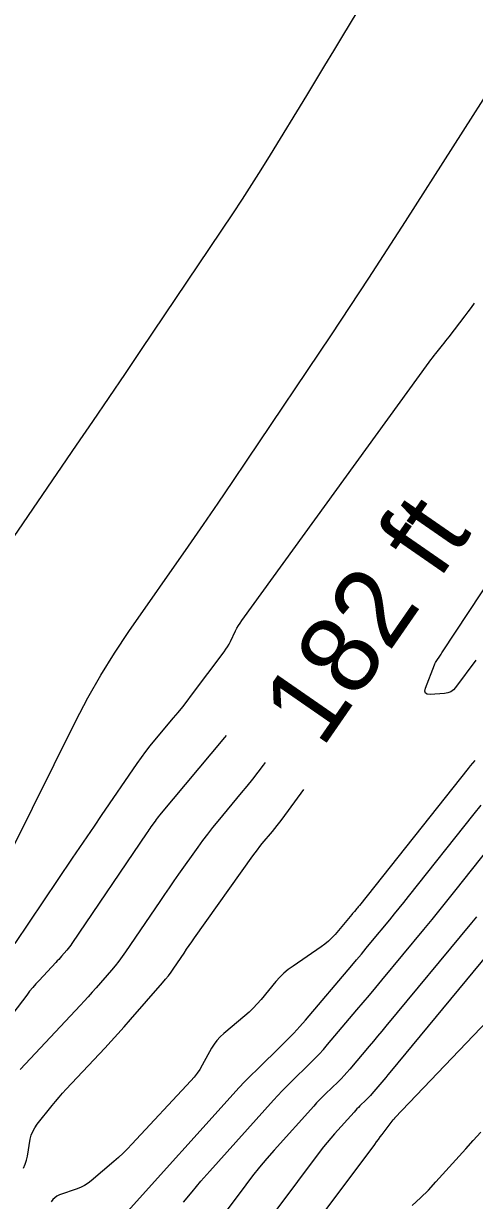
# Model space of a CAD drawing. Extents: x 7585033 to 7595090, y 547091 to 553471.
# Drawn here: x 7587281.3 to 7587317.3, y 548010.4 to 548104.5 of the extents above; entities that cross this region are included whole.
import ezdxf

# ---------------------------------------------------------------- set-up
doc = ezdxf.new("R2010")
doc.units = 0
for name, color, linetype in [('E_TERR_DSPLAY_GeneralTx', 7, 'Continuous'), ('E_TERR_DSPLAY_MajContour', 7, 'Continuous'), ('E_TERR_DSPLAY_MinContour', 7, 'Continuous')]:
    doc.layers.add(name, color=color, linetype=linetype)

msp = doc.modelspace()

# ---------------------------------------------------------------- linework, layer by layer
at = {"layer": 'E_TERR_DSPLAY_MajContour'}
for points in [[(7587316.39, 548119.453), (7587306.779, 548103.554), (7587306.057, 548102.36), (7587305.334, 548101.168), (7587304.61, 548099.976), (7587303.885, 548098.784), (7587300.983, 548094.02), (7587300.252, 548092.833), (7587299.506, 548091.654), (7587298.748, 548090.484), (7587297.977, 548089.322), (7587290.68, 548078.465), (7587289.388, 548076.547), (7587288.091, 548074.633), (7587286.79, 548072.722), (7587285.484, 548070.815), (7587279.269, 548061.761)], [(7587300.583, 548045.442), (7587300.43, 548045.234), (7587300.006, 548044.667), (7587299.573, 548044.106), (7587299.132, 548043.552), (7587298.682, 548043.005), (7587296.804, 548040.755), (7587296.386, 548040.244), (7587295.978, 548039.725), (7587295.58, 548039.198), (7587295.193, 548038.664), (7587293.662, 548036.509), (7587293.281, 548035.97), (7587292.903, 548035.428), (7587292.528, 548034.884), (7587292.157, 548034.338), (7587289.432, 548030.311), (7587289.164, 548029.928), (7587288.885, 548029.553), (7587288.595, 548029.187), (7587288.293, 548028.83), (7587287.064, 548027.417), (7587286.756, 548027.066), (7587286.444, 548026.717), (7587286.128, 548026.371), (7587285.81, 548026.028), (7587281.005, 548020.901)], [(7587289.593, 548009.532), (7587298.026, 548018.916), (7587298.492, 548019.426), (7587298.967, 548019.927), (7587299.45, 548020.42), (7587299.942, 548020.905), (7587301.926, 548022.827), (7587302.416, 548023.314), (7587302.893, 548023.812), (7587303.358, 548024.322), (7587303.811, 548024.843), (7587307.518, 548029.221), (7587307.901, 548029.674), (7587308.283, 548030.129), (7587308.663, 548030.585), (7587309.042, 548031.042), (7587310.557, 548032.872), (7587310.934, 548033.331), (7587311.309, 548033.791), (7587311.682, 548034.253), (7587312.053, 548034.717), (7587317.311, 548041.334), (7587317.876, 548042.039)], [(7587293.366, 547993.545), (7587309.35, 548014.904), (7587309.499, 548015.103), (7587309.648, 548015.302), (7587309.797, 548015.501), (7587309.946, 548015.699), (7587310.83, 548016.875), (7587310.837, 548016.883), (7587310.844, 548016.891), (7587310.851, 548016.898), (7587310.86, 548016.905), (7587310.895, 548016.934), (7587310.903, 548016.94), (7587310.91, 548016.947), (7587310.916, 548016.953), (7587310.923, 548016.96), (7587310.948, 548016.989), (7587310.961, 548017.003), (7587310.974, 548017.017), (7587323.542, 548030.193)]]:
    msp.add_lwpolyline(points, dxfattribs=at)
at = {"layer": 'E_TERR_DSPLAY_MinContour'}
for points in [[(7587278.496, 548034.795), (7587285.457, 548048.771), (7587286.419, 548050.616), (7587287.446, 548052.422), (7587288.538, 548054.189), (7587289.697, 548055.917), (7587294.461, 548062.752), (7587295.648, 548064.464), (7587296.828, 548066.18), (7587298, 548067.902), (7587299.164, 548069.629), (7587305.888, 548079.652), (7587307.389, 548081.903), (7587308.877, 548084.163), (7587310.352, 548086.431), (7587311.813, 548088.708), (7587323.254, 548106.648)], [(7587280.603, 548030.96), (7587285.192, 548037.783), (7587285.77, 548038.641), (7587286.35, 548039.497), (7587286.931, 548040.353), (7587287.514, 548041.207), (7587290.359, 548045.37), (7587290.693, 548045.846), (7587291.038, 548046.313), (7587291.395, 548046.771), (7587291.763, 548047.22), (7587293.259, 548049.001), (7587293.63, 548049.448), (7587293.994, 548049.901), (7587294.352, 548050.358), (7587294.704, 548050.821), (7587297.317, 548054.304), (7587297.455, 548054.498), (7587297.584, 548054.697), (7587297.702, 548054.903), (7587297.811, 548055.115), (7587298.228, 548055.973), (7587298.337, 548056.185), (7587298.455, 548056.391), (7587298.581, 548056.592), (7587298.717, 548056.788), (7587313.719, 548077.46), (7587313.847, 548077.634), (7587313.976, 548077.805), (7587314.108, 548077.975), (7587314.241, 548078.143), (7587314.78, 548078.813), (7587314.914, 548078.981), (7587315.047, 548079.149), (7587315.18, 548079.319), (7587315.311, 548079.489), (7587316.585, 548081.156), (7587316.838, 548081.492), (7587317.088, 548081.832), (7587317.332, 548082.175)], [(7587317.44, 548053.631), (7587315.826, 548051.451), (7587315.643, 548051.249), (7587315.432, 548051.1), (7587315.192, 548051.003), (7587314.923, 548050.958), (7587313.792, 548050.883), (7587313.557, 548050.9), (7587313.418, 548050.988), (7587313.374, 548051.146), (7587313.426, 548051.376), (7587314.125, 548053.241), (7587314.164, 548053.337), (7587314.209, 548053.43), (7587314.26, 548053.519), (7587314.316, 548053.606), (7587314.554, 548053.947), (7587314.613, 548054.032), (7587314.672, 548054.118), (7587314.73, 548054.204), (7587314.787, 548054.291), (7587321.996, 548065.221)], [(7587297.462, 548047.603), (7587297.335, 548047.448), (7587292.142, 548041.225), (7587292.05, 548041.113), (7587291.96, 548040.998), (7587291.872, 548040.882), (7587291.787, 548040.764), (7587291.449, 548040.289), (7587291.365, 548040.17), (7587291.282, 548040.051), (7587291.199, 548039.931), (7587291.117, 548039.81), (7587285.134, 548030.965), (7587285.039, 548030.83), (7587284.941, 548030.698), (7587284.838, 548030.569), (7587284.732, 548030.443), (7587284.299, 548029.945), (7587284.19, 548029.821), (7587284.08, 548029.698), (7587283.969, 548029.576), (7587283.856, 548029.455), (7587282.508, 548028.017), (7587282.25, 548027.734), (7587281.998, 548027.445), (7587281.754, 548027.149), (7587281.518, 548026.848), (7587276.677, 548020.517)], [(7587317.348, 548045.602), (7587317.168, 548045.386), (7587316.991, 548045.169), (7587316.815, 548044.95), (7587308.125, 548034.013), (7587308.077, 548033.953), (7587308.028, 548033.892), (7587307.979, 548033.832), (7587307.93, 548033.772), (7587307.732, 548033.533), (7587307.682, 548033.474), (7587307.633, 548033.414), (7587307.583, 548033.355), (7587307.533, 548033.296), (7587306.178, 548031.696), (7587305.927, 548031.419), (7587305.659, 548031.16), (7587305.374, 548030.921), (7587305.073, 548030.7), (7587302.818, 548029.163), (7587302.444, 548028.889), (7587302.092, 548028.591), (7587301.763, 548028.269), (7587301.455, 548027.922), (7587300.267, 548026.489), (7587299.963, 548026.139), (7587299.643, 548025.802), (7587299.309, 548025.481), (7587298.96, 548025.174), (7587297.278, 548023.762), (7587296.995, 548023.502), (7587296.739, 548023.22), (7587296.51, 548022.915), (7587296.309, 548022.588), (7587295.555, 548021.236), (7587295.358, 548020.905), (7587295.141, 548020.588), (7587294.906, 548020.284), (7587294.652, 548019.994), (7587289.94, 548014.927), (7587289.592, 548014.563), (7587289.233, 548014.21), (7587288.865, 548013.868), (7587288.486, 548013.536), (7587286.68, 548012.002), (7587286.423, 548011.803), (7587286.151, 548011.63), (7587285.864, 548011.482), (7587285.563, 548011.36), (7587284.146, 548010.86), (7587283.94, 548010.767), (7587283.761, 548010.643), (7587283.608, 548010.488), (7587283.482, 548010.301)], [(7587281.262, 548013.011), (7587281.398, 548013.317), (7587281.503, 548013.635), (7587281.577, 548013.966), (7587281.809, 548015.311), (7587281.886, 548015.639), (7587282.003, 548015.949), (7587282.158, 548016.241), (7587282.352, 548016.516), (7587283.55, 548018.008), (7587283.824, 548018.343), (7587284.104, 548018.672), (7587284.39, 548018.996), (7587284.683, 548019.314), (7587287.763, 548022.601), (7587288.288, 548023.166), (7587288.807, 548023.736), (7587289.321, 548024.31), (7587289.83, 548024.89), (7587292.385, 548027.825), (7587292.621, 548028.106), (7587292.849, 548028.393), (7587293.068, 548028.687), (7587293.278, 548028.988), (7587294.102, 548030.205), (7587294.308, 548030.508), (7587294.517, 548030.811), (7587294.727, 548031.112), (7587294.939, 548031.412), (7587299.597, 548037.968), (7587299.781, 548038.222), (7587299.97, 548038.472), (7587300.163, 548038.719), (7587300.362, 548038.961), (7587301.166, 548039.925), (7587301.365, 548040.167), (7587301.561, 548040.413), (7587301.753, 548040.661), (7587301.94, 548040.912), (7587303.691, 548043.291)], [(7587294.061, 548010.275), (7587294.741, 548011.124), (7587295.441, 548011.957), (7587296.159, 548012.775), (7587301.25, 548018.44), (7587301.599, 548018.822), (7587301.955, 548019.197), (7587302.317, 548019.567), (7587302.685, 548019.93), (7587304.172, 548021.37), (7587304.539, 548021.735), (7587304.897, 548022.108), (7587305.246, 548022.49), (7587305.585, 548022.881), (7587307.932, 548025.653), (7587308.434, 548026.247), (7587308.934, 548026.843), (7587309.432, 548027.44), (7587309.929, 548028.039), (7587313.292, 548032.102), (7587313.944, 548032.894), (7587314.592, 548033.69), (7587315.236, 548034.488), (7587315.876, 548035.289), (7587318.429, 548038.502)], [(7587317.488, 548033.101), (7587317.093, 548032.622), (7587310.25, 548024.351), (7587309.919, 548023.953), (7587309.587, 548023.555), (7587309.254, 548023.159), (7587308.921, 548022.763), (7587307.358, 548020.919), (7587307.133, 548020.659), (7587306.901, 548020.404), (7587306.663, 548020.156), (7587306.419, 548019.914), (7587305.429, 548018.955), (7587305.184, 548018.713), (7587304.943, 548018.467), (7587304.706, 548018.217), (7587304.474, 548017.963), (7587301.322, 548014.455), (7587300.727, 548013.779), (7587300.149, 548013.09), (7587299.586, 548012.388), (7587299.038, 548011.673), (7587291.23, 548001.239)], [(7587320.895, 548033.142), (7587310.57, 548020.663), (7587310.406, 548020.465), (7587310.241, 548020.267), (7587310.075, 548020.07), (7587309.909, 548019.874), (7587309.132, 548018.956), (7587309.02, 548018.827), (7587308.905, 548018.701), (7587308.786, 548018.577), (7587308.665, 548018.457), (7587308.173, 548017.98), (7587308.051, 548017.86), (7587307.931, 548017.737), (7587307.813, 548017.613), (7587307.698, 548017.487), (7587306.13, 548015.742), (7587305.835, 548015.406), (7587305.547, 548015.063), (7587305.267, 548014.714), (7587304.995, 548014.359), (7587292.298, 547997.392)], [(7587312.359, 548010.029), (7587313.016, 548010.628), (7587313.647, 548011.253), (7587314.254, 548011.904), (7587316.631, 548014.561), (7587317.228, 548015.223), (7587317.83, 548015.88)]]:
    msp.add_lwpolyline(points, dxfattribs=at)

# ---------------------------------------------------------------- texts
at = {"layer": 'E_TERR_DSPLAY_GeneralTx'}
msp.add_text('182 ft', height=6.3, rotation=55.30447, dxfattribs=at).set_placement((7587305.144, 548046.496))

doc.saveas('drawing.dxf')
